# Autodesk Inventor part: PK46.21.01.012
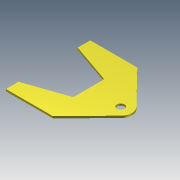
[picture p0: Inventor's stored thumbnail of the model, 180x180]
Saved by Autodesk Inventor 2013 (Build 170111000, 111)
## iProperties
Created: 2005-04
Part Number: PK46.21.01.012
Material: Steel, Mild
Document SubType Name: Modeling
Designer: salex
Manufacturer: Standard
Standards Organization: Custom
Density: 7.86 g/cm^3
Author: salex
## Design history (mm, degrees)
sketch "Эскиз1"
  geometry: L1 (0, 0)-(-241.647, 0); L2 (82.167, 80.458)-(-265, 435); L3 (-265, 435)-(-750, 435); L4 (-750, 435)-(-750, 305); L5 (-750, 305)-(-330, 160); L6 (-330, 160)-(-330, -160); L7 (82.167, -80.458)-(-265, -435); L8 (-265, -435)-(-750, -435); L9 (-750, -305)-(-330, -160); L10 (-750, -435)-(-750, -305); C1 r 40 at (0, 0); A1 r 115 centre (0, 0) between (82.167, -80.458) and (82.167, 80.458)
  constraints: 20 end point, 4 symmetric about line, 2 centre point, 2 point on circle, 1 coincident, 1 equal length, 1 horizontal, 1 parallel, 1 perpendicular, 1 tangent, 1 other
  dimensions: "d0" = 115 radius of A1; "d1" = 80 diameter of C1; "d2" = 750 distance from line of L4 C1.centre; "d3" = 870 diameter of L3 L1; "d4" = 130 distance of L3.end L4.end; "d5" = 330 distance from line of C1.centre L6; "d9" = 265 horizontal distance of L2.end L1.start; "d17" = 275 distance from line of L6.end L8; "d18" = 275 distance from line of L5.end L3 (= d17)
extrude "Выдавливание1" new body sketch "Эскиз1" distance "d11" = 20; taper "d12" = 0 deg
fillet "Сопряжение2" dims "d19" = 20
body "Solid1"
